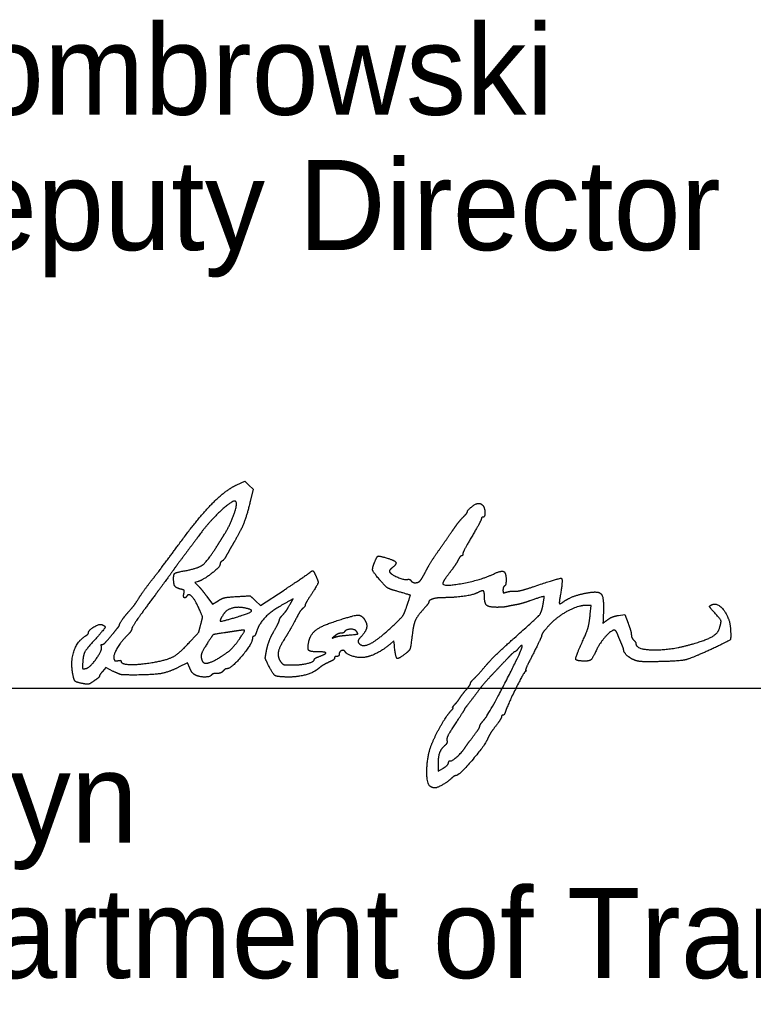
# Model space of a CAD drawing. Extents: x 0 to 34, y 0 to 22.
# Drawn here: x 25.676 to 26.815, y 9.207 to 10.736 of the extents above; entities that cross this region are included whole.
import ezdxf

# ---------------------------------------------------------------- set-up
doc = ezdxf.new("R2010")
doc.units = 0
doc.layers.add('SH_Data', color=7, linetype='Continuous')
doc.layers.add('SH_Text', color=7, linetype='Continuous')

msp = doc.modelspace()

# ---------------------------------------------------------------- linework, layer by layer
at = {"layer": 'SH_Data'}
msp.add_line((24.5279, 9.6988), (28.0279, 9.6988), dxfattribs=at)
at = {"layer": 'SH_Text'}
for points in [[(26.0131, 10.014), (26.0258, 10.0199), (26.0321, 10.0135), (26.0385, 10.0071), (26.0341, 9.9884)], [(25.9532, 9.864), (25.9482, 9.8625), (25.9534, 9.8573)], [(26.0422, 9.8343), (26.0503, 9.8267), (26.0866, 9.8508)], [(25.967, 9.8406), (25.9756, 9.8291), (25.9844, 9.8343)], [(26.0961, 9.8291), (26.1005, 9.837), (26.095, 9.8341)], [(26.5619, 9.8132), (26.5634, 9.827), (26.5556, 9.827)], [(26.6058, 9.8115), (26.6154, 9.8131), (26.6205, 9.7995)], [(26.2578, 9.7654), (26.2572, 9.7722), (26.2513, 9.7671)], [(25.8216, 9.7247), (25.8101, 9.7305), (25.805, 9.7247)], [(25.9402, 9.7298), (25.9369, 9.7378), (25.923, 9.731)], [(26.3256, 9.5793), (26.3256, 9.5699), (26.3331, 9.5742)]]:
    msp.add_lwpolyline(points, dxfattribs=at)
for points in [[(25.9236, 9.9221), (25.9533, 9.9627), (25.9951, 10.0056), (26.0131, 10.014)], [(26.0117, 9.9882), (26.008, 9.9919), (25.9695, 9.9561), (25.9541, 9.9348)], [(25.9934, 9.9362), (26.0028, 9.951), (26.0148, 9.9851), (26.0117, 9.9882)], [(26.0341, 9.9884), (26.0291, 9.9673), (26.0199, 9.9437), (26.0105, 9.9278)], [(26.3712, 9.9721), (26.3712, 9.9749), (26.3844, 9.9852), (26.3881, 9.9853)], [(26.3881, 9.9853), (26.3901, 9.9853), (26.3931, 9.9841), (26.3947, 9.9825)], [(26.3646, 9.964), (26.3682, 9.9676), (26.3712, 9.9713), (26.3712, 9.9721)], [(26.3947, 9.9825), (26.3982, 9.979), (26.3986, 9.9638), (26.3952, 9.9638)], [(26.3508, 9.9468), (26.3547, 9.9526), (26.361, 9.9603), (26.3646, 9.964)], [(26.3928, 9.9612), (26.3928, 9.9599), (26.3863, 9.9478), (26.3784, 9.9344)], [(26.3952, 9.9638), (26.3939, 9.9638), (26.3928, 9.9626), (26.3928, 9.9612)], [(26.3292, 9.9158), (26.3371, 9.927), (26.3468, 9.9409), (26.3508, 9.9468)], [(25.9541, 9.9348), (25.9505, 9.9299), (25.9411, 9.9172), (25.9332, 9.9067)], [(25.9829, 9.9195), (25.9861, 9.9247), (25.9909, 9.9322), (25.9934, 9.9362)], [(26.0105, 9.9278), (26.007, 9.9218), (26.0018, 9.9126), (25.9989, 9.9074)], [(26.3784, 9.9344), (26.3705, 9.921), (26.364, 9.9086), (26.364, 9.9069)], [(25.8834, 9.8687), (25.8923, 9.88), (25.9104, 9.9041), (25.9236, 9.9221)], [(25.9331, 9.8808), (25.9537, 9.8846), (25.9677, 9.8955), (25.9829, 9.9195)], [(26.3078, 9.8822), (26.3116, 9.8894), (26.3212, 9.9045), (26.3292, 9.9158)], [(25.9332, 9.9067), (25.9253, 9.8962), (25.9172, 9.8852), (25.9152, 9.8823)], [(25.9905, 9.8958), (25.9887, 9.8948), (25.9872, 9.8924), (25.9872, 9.8904)], [(25.9989, 9.9074), (25.9961, 9.9021), (25.9923, 9.8969), (25.9905, 9.8958)], [(26.2369, 9.8646), (26.2254, 9.8777), (26.2232, 9.8844), (26.2271, 9.894)], [(26.2271, 9.894), (26.2309, 9.9031), (26.234, 9.9041), (26.2467, 9.9003)], [(26.2467, 9.9003), (26.2587, 9.8968), (26.2616, 9.8906), (26.2539, 9.8848)], [(26.3567, 9.8972), (26.3549, 9.8935), (26.3488, 9.8844), (26.3431, 9.877)], [(26.362, 9.9038), (26.3609, 9.9038), (26.3585, 9.9008), (26.3567, 9.8972)], [(26.364, 9.9069), (26.364, 9.9052), (26.3631, 9.9038), (26.362, 9.9038)], [(25.9152, 9.8823), (25.9132, 9.8793), (25.8978, 9.8584), (25.881, 9.8357)], [(25.9152, 9.8687), (25.9152, 9.8756), (25.9193, 9.8784), (25.9331, 9.8808)], [(25.9872, 9.8904), (25.9872, 9.8867), (25.9614, 9.8666), (25.9532, 9.864)], [(26.1257, 9.8773), (26.1302, 9.8811), (26.1326, 9.8802), (26.1356, 9.8736)], [(26.2539, 9.8848), (26.2512, 9.8827), (26.2497, 9.8798), (26.2506, 9.8785)], [(26.2506, 9.8785), (26.2533, 9.8747), (26.2732, 9.8665), (26.2778, 9.8673)], [(26.2985, 9.866), (26.2998, 9.8676), (26.304, 9.8749), (26.3078, 9.8822)], [(26.4104, 9.8751), (26.4233, 9.8813), (26.4312, 9.8782), (26.4312, 9.8668)], [(25.8619, 9.8393), (25.8648, 9.8441), (25.8745, 9.8573), (25.8834, 9.8687)], [(25.9262, 9.8523), (25.919, 9.8541), (25.9152, 9.8598), (25.9152, 9.8687)], [(26.0866, 9.8508), (26.1065, 9.8641), (26.1241, 9.876), (26.1257, 9.8773)], [(26.1356, 9.8736), (26.14, 9.864), (26.139, 9.8599), (26.1288, 9.844)], [(26.2604, 9.8494), (26.2496, 9.8526), (26.2447, 9.8557), (26.2369, 9.8646)], [(26.2778, 9.8673), (26.2801, 9.8677), (26.2827, 9.8669), (26.2835, 9.8655)], [(26.2835, 9.8655), (26.2857, 9.862), (26.2957, 9.8623), (26.2985, 9.866)], [(26.3431, 9.877), (26.3374, 9.8695), (26.3328, 9.8622), (26.3328, 9.8609)], [(26.3328, 9.8609), (26.3328, 9.8556), (26.3924, 9.8666), (26.4104, 9.8751)], [(26.4312, 9.8668), (26.4312, 9.8622), (26.4301, 9.8578), (26.4288, 9.857)], [(26.4735, 9.856), (26.5139, 9.8699), (26.5198, 9.8683), (26.5157, 9.8444)], [(25.9313, 9.8461), (25.9322, 9.8496), (25.9309, 9.8511), (25.9262, 9.8523)], [(25.9534, 9.8573), (25.9562, 9.8545), (25.9623, 9.847), (25.967, 9.8406)], [(26.2772, 9.8257), (26.2828, 9.8425), (26.2825, 9.8431), (26.2604, 9.8494)], [(26.3976, 9.8416), (26.3976, 9.8489), (26.3939, 9.8505), (26.3861, 9.8463)], [(26.4288, 9.857), (26.4275, 9.8561), (26.4264, 9.8533), (26.4264, 9.8507)], [(26.4264, 9.8507), (26.4264, 9.8467), (26.4274, 9.8462), (26.4318, 9.8476)], [(26.4318, 9.8476), (26.4348, 9.8485), (26.4406, 9.8492), (26.4447, 9.849)], [(26.4447, 9.849), (26.4489, 9.8488), (26.4618, 9.852), (26.4735, 9.856)], [(26.5608, 9.8471), (26.5754, 9.8494), (26.5831, 9.839), (26.5823, 9.8177)], [(25.8456, 9.8174), (25.8522, 9.8248), (25.8564, 9.8305), (25.8619, 9.8393)], [(25.881, 9.8357), (25.8643, 9.8131), (25.8505, 9.7929), (25.8504, 9.791)], [(25.9355, 9.8413), (25.9331, 9.8374), (25.9299, 9.8409), (25.9313, 9.8461)], [(25.9543, 9.8227), (25.9482, 9.8364), (25.9385, 9.846), (25.9355, 9.8413)], [(25.9844, 9.8343), (25.9909, 9.8382), (25.9985, 9.8399), (26.0136, 9.8408)], [(26.0136, 9.8408), (26.0339, 9.842), (26.0341, 9.8419), (26.0422, 9.8343)], [(26.095, 9.8341), (26.0716, 9.8215), (26.0488, 9.8009), (26.0447, 9.7884)], [(26.1288, 9.844), (26.1235, 9.8359), (26.1192, 9.8283), (26.1192, 9.8272)], [(26.3354, 9.839), (26.3239, 9.839), (26.3112, 9.8352), (26.3112, 9.8318)], [(26.3861, 9.8463), (26.3806, 9.8433), (26.3504, 9.839), (26.3354, 9.839)], [(26.4169, 9.824), (26.4045, 9.824), (26.3976, 9.8303), (26.3976, 9.8416)], [(26.4682, 9.8341), (26.4604, 9.8314), (26.4507, 9.8286), (26.4468, 9.828)], [(26.4888, 9.8294), (26.4909, 9.8409), (26.4891, 9.8413), (26.4682, 9.8341)], [(26.5157, 9.8444), (26.5143, 9.8368), (26.5136, 9.8302), (26.5141, 9.8297)], [(26.5141, 9.8297), (26.5145, 9.8292), (26.5179, 9.831), (26.5216, 9.8336)], [(26.5216, 9.8336), (26.5289, 9.8386), (26.5471, 9.8449), (26.5608, 9.8471)], [(25.8312, 9.797), (25.8312, 9.7986), (25.8403, 9.8116), (25.8456, 9.8174)], [(25.9576, 9.7982), (25.9602, 9.808), (25.9599, 9.8102), (25.9543, 9.8227)], [(26.0254, 9.823), (26.0145, 9.8252), (25.9971, 9.8201), (25.9928, 9.8135)], [(26.0148, 9.8095), (26.034, 9.8154), (26.038, 9.8205), (26.0254, 9.823)], [(26.0833, 9.8109), (26.0887, 9.8169), (26.0912, 9.8205), (26.0961, 9.8291)], [(26.1156, 9.8222), (26.1137, 9.8206), (26.1106, 9.8164), (26.1087, 9.8129)], [(26.1192, 9.8272), (26.1192, 9.8261), (26.1176, 9.8238), (26.1156, 9.8222)], [(26.2589, 9.7984), (26.2693, 9.8084), (26.2734, 9.8146), (26.2772, 9.8257)], [(26.3018, 9.8197), (26.2933, 9.8103), (26.2876, 9.7977), (26.286, 9.785)], [(26.3112, 9.8318), (26.3112, 9.8309), (26.307, 9.8255), (26.3018, 9.8197)], [(26.4336, 9.8254), (26.4303, 9.8246), (26.4228, 9.824), (26.4169, 9.824)], [(26.4468, 9.828), (26.4428, 9.8273), (26.4369, 9.8262), (26.4336, 9.8254)], [(26.4439, 9.7764), (26.4795, 9.808), (26.4864, 9.8162), (26.4888, 9.8294)], [(26.5556, 9.827), (26.5429, 9.827), (26.5091, 9.8085), (26.4969, 9.795)], [(26.5823, 9.8177), (26.5816, 9.7993), (26.5815, 9.7996), (26.5892, 9.8051)], [(26.7524, 9.8183), (26.7471, 9.824), (26.7468, 9.8267), (26.7515, 9.8284)], [(26.7515, 9.8284), (26.76, 9.8317), (26.7785, 9.8068), (26.7795, 9.7905)], [(26.7615, 9.7892), (26.7655, 9.801), (26.7639, 9.8059), (26.7524, 9.8183)], [(25.9928, 9.8135), (25.9858, 9.8028), (25.9903, 9.802), (26.0148, 9.8095)], [(26.0708, 9.7868), (26.0752, 9.7945), (26.079, 9.8022), (26.0793, 9.8039)], [(26.0793, 9.8039), (26.0796, 9.8057), (26.0813, 9.8088), (26.0833, 9.8109)], [(26.1087, 9.8129), (26.1006, 9.7975), (26.0928, 9.7837), (26.0867, 9.774)], [(26.1626, 9.8012), (26.1944, 9.8118), (26.2078, 9.8122), (26.2129, 9.8028)], [(26.2129, 9.8028), (26.2161, 9.7967), (26.2127, 9.7853), (26.2053, 9.7774)], [(26.5472, 9.7653), (26.5563, 9.7852), (26.5603, 9.7984), (26.5619, 9.8132)], [(26.5892, 9.8051), (26.593, 9.8078), (26.6004, 9.8107), (26.6058, 9.8115)], [(25.7832, 9.7849), (25.7833, 9.7887), (25.8, 9.7987), (25.8038, 9.7972)], [(25.8038, 9.7972), (25.8098, 9.7949), (25.8075, 9.79), (25.7932, 9.7741)], [(25.8167, 9.7778), (25.822, 9.7844), (25.8275, 9.7911), (25.8288, 9.7927)], [(25.8288, 9.7927), (25.8301, 9.7943), (25.8312, 9.7962), (25.8312, 9.797)], [(25.8504, 9.791), (25.8503, 9.789), (25.847, 9.7842), (25.843, 9.7802)], [(25.938, 9.7677), (25.9541, 9.7852), (25.9544, 9.7858), (25.9576, 9.7982)], [(26.013, 9.7874), (26.0074, 9.7865), (25.9995, 9.7853), (25.9956, 9.7847)], [(26.018, 9.7757), (26.0258, 9.7871), (26.0249, 9.7892), (26.013, 9.7874)], [(26.0447, 9.7884), (26.043, 9.7832), (26.0407, 9.779), (26.0396, 9.779)], [(26.0599, 9.759), (26.0615, 9.7667), (26.0664, 9.7792), (26.0708, 9.7868)], [(26.1249, 9.7701), (26.1271, 9.7814), (26.1433, 9.7948), (26.1626, 9.8012)], [(26.1987, 9.787), (26.1959, 9.7904), (26.1825, 9.7896), (26.1802, 9.7859)], [(26.1828, 9.7806), (26.1995, 9.7821), (26.2019, 9.7831), (26.1987, 9.787)], [(26.2019, 9.7695), (26.2072, 9.7609), (26.2339, 9.7744), (26.2589, 9.7984)], [(26.4969, 9.795), (26.4911, 9.7885), (26.4864, 9.782), (26.4864, 9.7804)], [(26.5988, 9.7886), (26.5945, 9.7886), (26.5762, 9.7681), (26.5715, 9.7579)], [(26.6044, 9.782), (26.6029, 9.7856), (26.6004, 9.7886), (26.5988, 9.7886)], [(26.6205, 9.7995), (26.6233, 9.7921), (26.6256, 9.7839), (26.6256, 9.7814)], [(26.7126, 9.765), (26.7363, 9.7712), (26.7593, 9.7826), (26.7615, 9.7892)], [(26.7795, 9.7905), (26.7804, 9.7752), (26.7778, 9.7721), (26.7544, 9.7611)], [(25.7583, 9.7233), (25.7554, 9.7418), (25.7661, 9.7719), (25.7785, 9.7796)], [(25.7932, 9.7741), (25.7795, 9.759), (25.7745, 9.7488), (25.7739, 9.735)], [(25.7785, 9.7796), (25.7811, 9.7812), (25.7832, 9.7836), (25.7832, 9.7849)], [(25.8044, 9.7665), (25.8058, 9.7661), (25.8113, 9.7712), (25.8167, 9.7778)], [(25.843, 9.7802), (25.8332, 9.7706), (25.8208, 9.7485), (25.8226, 9.7438)], [(25.9956, 9.7847), (25.9778, 9.7821), (25.9758, 9.781), (25.9685, 9.7698)], [(25.9881, 9.747), (25.9993, 9.754), (26.0102, 9.7646), (26.018, 9.7757)], [(26.0375, 9.776), (26.0374, 9.7674), (26.0043, 9.7286), (25.9972, 9.7286)], [(26.0396, 9.779), (26.0385, 9.779), (26.0376, 9.7776), (26.0375, 9.776)], [(26.0867, 9.774), (26.0787, 9.7614), (26.0765, 9.7462), (26.0816, 9.7394)], [(26.1658, 9.78), (26.1612, 9.7762), (26.1612, 9.7762), (26.166, 9.7779)], [(26.1747, 9.7838), (26.1724, 9.7838), (26.1684, 9.782), (26.1658, 9.78)], [(26.166, 9.7779), (26.1686, 9.7788), (26.1762, 9.78), (26.1828, 9.7806)], [(26.1802, 9.7859), (26.1795, 9.7847), (26.177, 9.7838), (26.1747, 9.7838)], [(26.2053, 9.7774), (26.2025, 9.7745), (26.201, 9.771), (26.2019, 9.7695)], [(26.286, 9.785), (26.2832, 9.7625), (26.2814, 9.757), (26.2758, 9.7525)], [(26.3999, 9.7337), (26.4071, 9.7421), (26.4269, 9.7613), (26.4439, 9.7764)], [(26.4864, 9.7804), (26.4864, 9.7788), (26.4804, 9.766), (26.4732, 9.7518)], [(26.6103, 9.7678), (26.6085, 9.772), (26.6058, 9.7783), (26.6044, 9.782)], [(26.6256, 9.7814), (26.6256, 9.7789), (26.6272, 9.7753), (26.6292, 9.7733)], [(26.6292, 9.7733), (26.6312, 9.7713), (26.6328, 9.7686), (26.6328, 9.7673)], [(25.7787, 9.729), (25.7851, 9.7299), (25.8052, 9.7584), (25.8032, 9.7636)], [(25.8032, 9.7636), (25.8024, 9.7655), (25.803, 9.7668), (25.8044, 9.7665)], [(25.8815, 9.7383), (25.9042, 9.742), (25.9238, 9.7522), (25.938, 9.7677)], [(25.9685, 9.7698), (25.9603, 9.7571), (25.9571, 9.7473), (25.9593, 9.7415)], [(26.0619, 9.735), (26.0575, 9.7441), (26.0573, 9.7463), (26.0599, 9.759)], [(26.1385, 9.755), (26.127, 9.755), (26.1229, 9.7595), (26.1249, 9.7701)], [(26.1815, 9.7551), (26.1795, 9.7584), (26.172, 9.7552), (26.172, 9.7511)], [(26.2513, 9.7671), (26.2419, 9.7589), (26.2219, 9.7483), (26.2128, 9.7466)], [(26.2758, 9.7525), (26.264, 9.7433), (26.2597, 9.7464), (26.2578, 9.7654)], [(26.3973, 9.6499), (26.4049, 9.6586), (26.4582, 9.7624), (26.4561, 9.7644)], [(26.4504, 9.7604), (26.448, 9.7574), (26.4454, 9.755), (26.4446, 9.755)], [(26.4561, 9.7644), (26.4554, 9.7652), (26.4528, 9.7633), (26.4504, 9.7604)], [(26.5546, 9.7406), (26.5401, 9.7406), (26.5385, 9.746), (26.5472, 9.7653)], [(26.5715, 9.7579), (26.5658, 9.7455), (26.5609, 9.7406), (26.5546, 9.7406)], [(26.6137, 9.7582), (26.6136, 9.7593), (26.6121, 9.7636), (26.6103, 9.7678)], [(26.6293, 9.7426), (26.6223, 9.746), (26.6138, 9.7544), (26.6137, 9.7582)], [(26.6328, 9.7673), (26.6328, 9.7588), (26.6834, 9.7573), (26.7126, 9.765)], [(26.7544, 9.7611), (26.7196, 9.7448), (26.6985, 9.74), (26.6592, 9.7396)], [(25.8226, 9.7438), (25.8235, 9.7414), (25.8258, 9.7405), (25.8288, 9.7413)], [(25.8288, 9.7413), (25.8314, 9.7419), (25.8336, 9.7416), (25.8336, 9.7405)], [(25.8336, 9.7405), (25.8336, 9.7359), (25.8592, 9.7347), (25.8815, 9.7383)], [(25.9593, 9.7415), (25.9614, 9.7362), (25.9749, 9.7389), (25.9881, 9.747)], [(26.0992, 9.7346), (26.1132, 9.7346), (26.1336, 9.7397), (26.1336, 9.7432)], [(26.1336, 9.7432), (26.1336, 9.7442), (26.1373, 9.7464), (26.1419, 9.748)], [(26.1419, 9.748), (26.1522, 9.7518), (26.1506, 9.755), (26.1385, 9.755)], [(26.1594, 9.7404), (26.152, 9.7371), (26.1444, 9.7326), (26.1402, 9.7291)], [(26.1648, 9.7453), (26.1648, 9.7439), (26.1624, 9.7417), (26.1594, 9.7404)], [(26.1684, 9.7478), (26.1664, 9.7478), (26.1648, 9.7467), (26.1648, 9.7453)], [(26.172, 9.7511), (26.172, 9.7493), (26.1704, 9.7478), (26.1684, 9.7478)], [(26.2128, 9.7466), (26.2042, 9.7451), (26.1844, 9.7504), (26.1815, 9.7551)], [(26.4358, 9.7472), (26.4317, 9.7429), (26.4212, 9.7318), (26.4124, 9.7225)], [(26.4446, 9.755), (26.4438, 9.755), (26.4399, 9.7514), (26.4358, 9.7472)], [(26.4732, 9.7518), (26.4659, 9.7377), (26.4607, 9.7261), (26.4618, 9.7261)], [(26.6592, 9.7396), (26.6442, 9.7394), (26.6339, 9.7405), (26.6293, 9.7426)], [(25.7739, 9.735), (25.7737, 9.7294), (25.7745, 9.7284), (25.7787, 9.729)], [(25.923, 9.731), (25.9074, 9.7232), (25.8823, 9.719), (25.8524, 9.719)], [(25.9484, 9.7192), (25.9458, 9.7206), (25.9421, 9.7254), (25.9402, 9.7298)], [(25.9972, 9.7286), (25.996, 9.7286), (25.9936, 9.7269), (25.992, 9.725)], [(26.0937, 9.7158), (26.0762, 9.7159), (26.0692, 9.7202), (26.0619, 9.735)], [(26.0816, 9.7394), (26.0844, 9.7356), (26.088, 9.7346), (26.0992, 9.7346)], [(26.1402, 9.7291), (26.1325, 9.7227), (26.1082, 9.7158), (26.0937, 9.7158)], [(26.3814, 9.7133), (26.3844, 9.7161), (26.3927, 9.7253), (26.3999, 9.7337)], [(26.4618, 9.7261), (26.4628, 9.7261), (26.4624, 9.7253), (26.461, 9.7243)], [(25.7749, 9.7056), (25.764, 9.7076), (25.7602, 9.7117), (25.7583, 9.7233)], [(25.8, 9.7171), (25.8, 9.7162), (25.7962, 9.7128), (25.7916, 9.7097)], [(25.805, 9.7247), (25.8022, 9.7215), (25.8, 9.7181), (25.8, 9.7171)], [(25.8524, 9.719), (25.8368, 9.719), (25.8309, 9.7201), (25.8216, 9.7247)], [(25.974, 9.719), (25.972, 9.7158), (25.9545, 9.7159), (25.9484, 9.7192)], [(25.9822, 9.7214), (25.9785, 9.7214), (25.9748, 9.7203), (25.974, 9.719)], [(25.992, 9.725), (25.9903, 9.723), (25.9859, 9.7214), (25.9822, 9.7214)], [(26.376, 9.7061), (26.376, 9.7072), (26.3785, 9.7105), (26.3814, 9.7133)], [(26.4124, 9.7225), (26.4036, 9.7133), (26.3937, 9.702), (26.3904, 9.6975)], [(26.461, 9.7243), (26.4583, 9.7225), (26.4331, 9.6715), (26.4301, 9.662)], [(25.7916, 9.7097), (25.7851, 9.7052), (25.7815, 9.7043), (25.7749, 9.7056)], [(26.3592, 9.6829), (26.3612, 9.686), (26.3658, 9.692), (26.3694, 9.6963)], [(26.3904, 9.6975), (26.3823, 9.6866), (26.3718, 9.6728), (26.3688, 9.6693)], [(26.3694, 9.6963), (26.373, 9.7005), (26.376, 9.7049), (26.376, 9.7061)], [(26.3514, 9.673), (26.3537, 9.6754), (26.3572, 9.6799), (26.3592, 9.6829)], [(26.3455, 9.6632), (26.3482, 9.6661), (26.3497, 9.6686), (26.3488, 9.6686)], [(26.3488, 9.6686), (26.3479, 9.6686), (26.3491, 9.6705), (26.3514, 9.673)], [(26.3664, 9.6654), (26.3664, 9.6648), (26.36, 9.6549), (26.3523, 9.6433)], [(26.3688, 9.6693), (26.3675, 9.6677), (26.3664, 9.6659), (26.3664, 9.6654)], [(26.3154, 9.6106), (26.3213, 9.6254), (26.3384, 9.6553), (26.3455, 9.6632)], [(26.3904, 9.6396), (26.3904, 9.6409), (26.3935, 9.6455), (26.3973, 9.6499)], [(26.424, 9.6541), (26.424, 9.6527), (26.4197, 9.6459), (26.4145, 9.639)], [(26.4262, 9.6566), (26.425, 9.6566), (26.424, 9.6554), (26.424, 9.6541)], [(26.4301, 9.662), (26.4292, 9.659), (26.4274, 9.6566), (26.4262, 9.6566)], [(26.3523, 9.6433), (26.3436, 9.6302), (26.3387, 9.6205), (26.3394, 9.6178)], [(26.3802, 9.6237), (26.3858, 9.6311), (26.3904, 9.6382), (26.3904, 9.6396)], [(26.4145, 9.639), (26.4093, 9.6321), (26.4042, 9.6241), (26.4031, 9.6213)], [(26.4031, 9.6213), (26.3994, 9.6114), (26.3583, 9.563), (26.3536, 9.563)], [(26.3676, 9.6065), (26.3689, 9.6086), (26.3746, 9.6164), (26.3802, 9.6237)], [(26.3136, 9.5461), (26.3076, 9.5499), (26.3089, 9.5942), (26.3154, 9.6106)], [(26.3357, 9.6092), (26.3298, 9.6039), (26.3256, 9.5916), (26.3256, 9.5793)], [(26.3394, 9.6178), (26.34, 9.6152), (26.3385, 9.6116), (26.3357, 9.6092)], [(26.3448, 9.5858), (26.3467, 9.5846), (26.3633, 9.5997), (26.3676, 9.6065)], [(26.3331, 9.5742), (26.3373, 9.5766), (26.3412, 9.5804), (26.3418, 9.5827)], [(26.3418, 9.5827), (26.3424, 9.585), (26.3438, 9.5864), (26.3448, 9.5858)], [(26.3461, 9.5584), (26.3399, 9.5527), (26.324, 9.5437), (26.3201, 9.5438)], [(26.3536, 9.563), (26.3522, 9.563), (26.3489, 9.5609), (26.3461, 9.5584)], [(26.3201, 9.5438), (26.3185, 9.5438), (26.3156, 9.5449), (26.3136, 9.5461)]]:
    msp.add_open_spline(points, degree=2, dxfattribs=at)

# ---------------------------------------------------------------- texts
for s, p in [('Michael G. Dombrowski', (24.5279, 10.5882)), ('District       Deputy Director', (24.5279, 10.3782)), ('Pamela Boratyn', (24.5279, 9.4588)), ('Director, Department of Transportation', (24.5279, 9.2488))]:
    msp.add_text(s, height=0.14, dxfattribs=at).set_placement(p)

doc.saveas('drawing.dxf')
